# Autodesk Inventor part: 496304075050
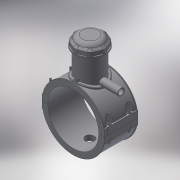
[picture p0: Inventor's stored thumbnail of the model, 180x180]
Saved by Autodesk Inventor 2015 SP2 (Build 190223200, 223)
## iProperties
Created: 2017-07
Part Number: 496304075050
Material: Generic
Description: PLASSON TAPPING SADDLE 75x50
Document SubType Name: Modeling
Designer: KIM
Mass: 706.717 g
Surface Area: 1731.79 cm^2
Volume: 706.717 cm^3
Density: 1 g/cm^3
Appearance: Default
Author: KIM
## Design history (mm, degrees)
derived "496304.ipt"
feature "Solid1::496304.ipt"
feature "Solid2::496304.ipt"
feature "Solid4::496304.ipt"
feature "Solid5::496304.ipt"
tag "TaggingFeature1"
body "Solid1"
body "Solid2"
other parameters: "d0" = 75, "d2" = 117, "d3" = 18.75, "d4" = 118, "d5" = 0, "d6" = 0.1, "d8" = 0, "d19" = 6, "d20" = 6, "d21" = 70.8, "d23" = 0, "d24" = 35.4, "d26" = 0, "d29" = 3, "d30" = 25, "d31" = 6, "d32" = 0, "d33" = 0, "d34" = 0.6, "d40" = 50.7, "d41" = 67.5, "d43" = 0, "d45" = 0, "d47" = 119.55, "d70" = 15, "d72" = 0, "d73" = 6, "d75" = 5, "d76" = 0, "d77" = 3.75, "d78" = 67.5, "d79" = 15, "d80" = 47.2, "d82" = 5 deg, "d84" = 4, "d85" = 14, "d86" = 0, "d87" = 3, "d88" = 0, "d89" = 1, "d90" = 1, "d91" = 94.4, "d92" = 0, "d93" = 0.5, "d94" = 39.47368, "d96" = 99.45, "d97" = 2.36, "d98" = 0, "d102" = 0.75, "d120" = 140 deg, "d121" = 24.228, "d122" = 20 deg, "d123" = 195, "d124" = 58.5, "d126" = 0, "d143" = 77.25, "d145" = 17.30769, "d149" = 1.125, "d150" = 19.03846, "d153" = 118, "d154" = 0, "d156" = 48.75, "d157" = 160 deg, "d159" = 4.5, "d161" = 1.125, "d162" = 70.8, "d163" = 0, "d164" = 37.5, "d167" = 7.5, "d168" = 47.56098, "d170" = 3.375, "d172" = 0, "d173" = 1, "d175" = 37.5, "d176" = 20 deg, "d177" = 5.25, "d178" = 22.5, "d180" = 0, "d183" = 9, "d184" = 4.2, "d185" = 38.35, "d186" = 38.35, "d187" = 48.75, "d188" = 6.75, "d189" = 5.25, "d190" = 0, "d191" = 73.125, "d193" = 6.3, "d194" = 4.13, "d195" = 90 deg, "d197" = 0, "d199" = 0, "d200" = 11.25, "d202" = 0, "d203" = 177, "d204" = 64.125, "d205" = 47.25, "d206" = 57.375, "d207" = 132.75, "d208" = 138.06, "d209" = 164.61, "d210" = 58.05, "d211" = 67.5, "d212" = 54, "d213" = 35.1, "d216" = 0, "d217" = 7.5, "d218" = 7.5, "d219" = 1.5, "d222" = 75, "d224" = 0, "d230" = 4.5, "d233" = 6, "d236" = 58.5, "d237" = 35.4, "d238" = 6.02433, "d240" = 35.4, "d241" = 35.4, "d242" = 35.4, "d243" = 6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
